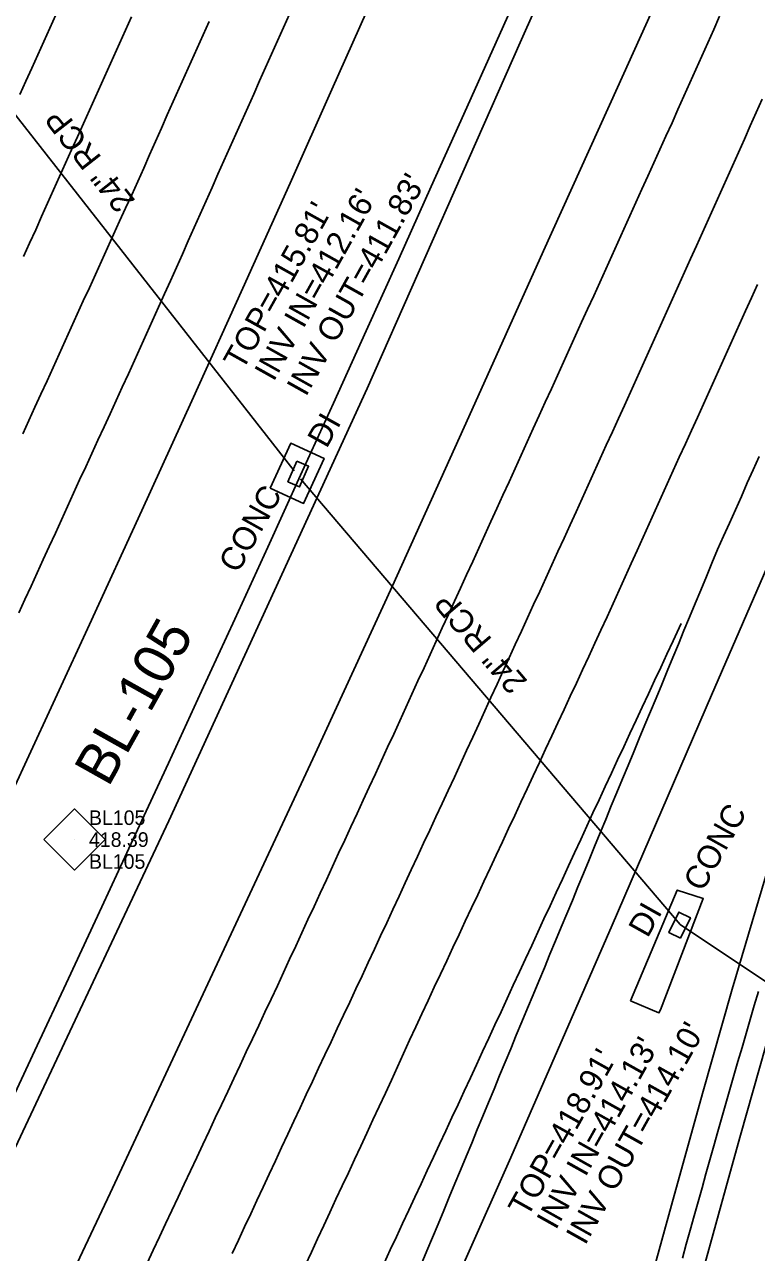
# Model space of a CAD drawing. Extents: x 2074109 to 2077820, y 741079 to 746031.
# Drawn here: x 2075964.7 to 2076090.1, y 744152.4 to 744362.7 of the extents above; entities that cross this region are included whole.
import ezdxf

# ---------------------------------------------------------------- set-up
doc = ezdxf.new("R2010")
doc.units = 0
for name, color, linetype in [('CTL Secondary Horizontal and Vertical CELL', 7, 'Continuous'), ('CTL Secondary Horizontal and Vertical Cogo Comment', 7, 'Continuous'), ('CTL Secondary Horizontal and Vertical Cogo Elevation', 7, 'Continuous'), ('CTL Secondary Horizontal and Vertical Cogo Number', 7, 'Continuous'), ('Exist Guardrail Cable Guide Rail', 7, 'Continuous'), ('Exist Horizontal Alignment', 7, 'Continuous'), ('Exist Horizontal Baseline Alignment Station Label', 7, 'Continuous'), ('Exist Roads EOP', 7, 'Continuous'), ('Exist Roads EOT', 7, 'Continuous'), ('Exist Structure Minor Drop Inlet', 7, 'Continuous'), ('Exist Structure Minor Drop Inlet Text', 7, 'Continuous'), ('Exist Structure Minor Drop Inlet Top Elevation', 7, 'Continuous'), ('Exist Structure Minor Paved Ditch or Gutter', 7, 'Continuous'), ('Exist Structure Minor Paved Ditch or Gutter Text', 7, 'Continuous'), ('Exist Structure Minor Pipes RCP 15 Inch', 7, 'Continuous'), ('Exist Structure Minor Pipes RCP 15 Inch Invert', 7, 'Continuous'), ('Exist Structure Minor Pipes RCP 24 Inch', 7, 'Continuous'), ('Exist Structure Minor Pipes RCP 24 Inch Invert', 7, 'Continuous'), ('Exist Structure Minor Pipes RCP 24 Inch Text', 7, 'Continuous')]:
    doc.layers.add(name, color=color, linetype=linetype)

msp = doc.modelspace()

# ---------------------------------------------------------------- linework, layer by layer
at = {"layer": 'CTL Secondary Horizontal and Vertical CELL'}
msp.add_line((2075973.22, 744223.13), (2075973.22, 744223.13), dxfattribs=at)
msp.add_lwpolyline([(2075968, 744223.15), (2075973.25, 744228.39), (2075978.5, 744223.14), (2075973.25, 744217.9)], close=True, dxfattribs=at)
at = {"layer": 'Exist Guardrail Cable Guide Rail'}
msp.add_lwpolyline([(2075948.31, 744139.02), (2075989.39, 744226.34), (2076023.39, 744300.35), (2076049.61, 744359.61), (2076088.84, 744447.64), (2076120.46, 744520.55), (2076157.81, 744608.48)], dxfattribs=at)
at = {"layer": 'Exist Horizontal Alignment'}
for centre, radius, start, end in [((2065746.77, 748969.72), 11283.45, 330.581241, 339.398504), ((2074798.58, 745361.18), 1469.76, 306.18995, 339.08912), ((2078824.82, 743400.1), 2844.34, 161.20687, 171.42865)]:
    msp.add_arc(centre, radius, start, end, dxfattribs=at)
at = {"layer": 'Exist Roads EOP'}
for points in [[(2076077.87, 744377.58), (2076066.3, 744351.92), (2076053.6, 744323.92), (2076040.8, 744295.48), (2076027.73, 744266.56), (2076014.5, 744237.8), (2076002.1, 744211.29), (2075990.51, 744186.45), (2075979.36, 744162.61), (2075967.54, 744137.56), (2075955.17, 744111.24)], [(2075952.83, 744210.32), (2075964.71, 744235.96), (2075975.8, 744259.95), (2075984.8, 744279.5), (2075993.35, 744298.22), (2076002.09, 744317.51), (2076010.19, 744335.52), (2076017.34, 744351.57), (2076024.53, 744367.7)], [(2076096.79, 744280.96), (2076082.4, 744247.87), (2076065.38, 744208.48), (2076047.99, 744168.72), (2076032.56, 744134.03)], [(2076070.12, 744140.88), (2076075.56, 744160.52), (2076080.83, 744179.63), (2076085.93, 744197.51), (2076092.78, 744220.6)]]:
    msp.add_lwpolyline(points, dxfattribs=at)
at = {"layer": 'Exist Roads EOT'}
for points in [[(2076010.08, 744364.46), (2076009.06, 744362.18), (2076008.04, 744359.9), (2076007.02, 744357.62), (2076005.99, 744355.34), (2076004.97, 744353.05), (2076003.95, 744350.77), (2076002.93, 744348.49), (2076001.91, 744346.21), (2076000.89, 744343.93), (2075999.87, 744341.64), (2075998.85, 744339.36), (2075997.83, 744337.08), (2075996.82, 744334.79), (2075995.8, 744332.51), (2075994.78, 744330.23), (2075993.76, 744327.94), (2075992.74, 744325.66), (2075991.73, 744323.38), (2075990.71, 744321.09), (2075989.68, 744318.81), (2075988.66, 744316.54), (2075987.63, 744314.26), (2075986.6, 744311.98), (2075985.57, 744309.7), (2075984.54, 744307.42), (2075983.52, 744305.14), (2075982.48, 744302.87), (2075981.43, 744300.6), (2075980.39, 744298.32), (2075979.35, 744296.05), (2075978.3, 744293.78), (2075977.26, 744291.51), (2075976.21, 744289.24), (2075975.17, 744286.97), (2075974.12, 744284.7), (2075973.08, 744282.43), (2075972.04, 744280.15), (2075971, 744277.88), (2075969.96, 744275.61), (2075968.92, 744273.33), (2075967.88, 744271.06), (2075966.84, 744268.79), (2075965.8, 744266.51), (2075964.76, 744264.24), (2075963.72, 744261.97)], [(2075963.89, 744350.68), (2075964.92, 744352.95), (2075965.94, 744355.23), (2075966.97, 744357.51), (2075968, 744359.79), (2075969.02, 744362.07), (2075970.05, 744364.35)], [(2075983.01, 744363.99), (2075981.99, 744361.71), (2075980.96, 744359.43), (2075979.94, 744357.15), (2075978.91, 744354.87), (2075977.89, 744352.59), (2075976.86, 744350.31), (2075975.83, 744348.03), (2075974.8, 744345.75), (2075973.77, 744343.47), (2075972.75, 744341.2), (2075971.72, 744338.92), (2075970.69, 744336.64), (2075969.67, 744334.36), (2075968.64, 744332.08), (2075967.61, 744329.8), (2075966.59, 744327.52), (2075965.56, 744325.24), (2075964.53, 744322.96)], [(2075985.67, 744150.58), (2075986.73, 744152.84), (2075987.8, 744155.11), (2075988.86, 744157.37), (2075989.92, 744159.63), (2075990.99, 744161.89), (2075992.05, 744164.15), (2075993.11, 744166.42), (2075994.18, 744168.68), (2075995.24, 744170.94), (2075996.3, 744173.2), (2075997.37, 744175.47), (2075998.43, 744177.73), (2075999.49, 744179.99), (2076000.56, 744182.25), (2076001.62, 744184.52), (2076002.68, 744186.78), (2076003.75, 744189.04), (2076004.81, 744191.3), (2076005.87, 744193.57), (2076006.93, 744195.83), (2076008, 744198.09), (2076009.05, 744200.36), (2076010.1, 744202.63), (2076011.15, 744204.9), (2076012.2, 744207.16), (2076013.25, 744209.43), (2076014.3, 744211.7), (2076015.35, 744213.97), (2076016.4, 744216.24), (2076017.45, 744218.51), (2076018.5, 744220.78), (2076019.55, 744223.04), (2076020.61, 744225.31), (2076021.66, 744227.58), (2076022.71, 744229.85), (2076023.76, 744232.12), (2076024.81, 744234.39), (2076025.85, 744236.66), (2076026.89, 744238.93), (2076027.94, 744241.2), (2076028.98, 744243.47), (2076030.02, 744245.75), (2076031.06, 744248.02), (2076032.1, 744250.29), (2076033.14, 744252.56), (2076034.18, 744254.84), (2076035.22, 744257.11), (2076036.27, 744259.38), (2076037.31, 744261.66), (2076038.35, 744263.93), (2076039.39, 744266.2), (2076040.43, 744268.47), (2076041.47, 744270.75), (2076042.51, 744273.02), (2076043.55, 744275.29), (2076044.59, 744277.57), (2076045.62, 744279.84), (2076046.66, 744282.12), (2076047.7, 744284.39), (2076048.74, 744286.67), (2076049.77, 744288.94), (2076050.81, 744291.21), (2076051.85, 744293.49), (2076052.89, 744295.76), (2076053.92, 744298.04), (2076054.96, 744300.31), (2076056, 744302.59), (2076057.04, 744304.86), (2076058.07, 744307.14), (2076059.11, 744309.41), (2076060.14, 744311.69), (2076061.17, 744313.96), (2076062.21, 744316.24), (2076063.24, 744318.52), (2076064.27, 744320.79), (2076065.3, 744323.07), (2076066.34, 744325.35), (2076067.37, 744327.62), (2076068.4, 744329.9), (2076069.43, 744332.18), (2076070.47, 744334.46), (2076071.5, 744336.73), (2076072.53, 744339.01), (2076073.56, 744341.29), (2076074.59, 744343.56), (2076075.63, 744345.84), (2076076.65, 744348.12), (2076077.67, 744350.4), (2076078.69, 744352.68), (2076079.71, 744354.97), (2076080.73, 744357.25), (2076081.75, 744359.53), (2076082.77, 744361.82), (2076083.79, 744364.1)], [(2075964.39, 744292.59), (2075965.43, 744294.86), (2075966.46, 744297.14), (2075967.5, 744299.41), (2075968.54, 744301.68), (2075969.57, 744303.96), (2075970.6, 744306.24), (2075971.64, 744308.51), (2075972.67, 744310.79), (2075973.71, 744313.06), (2075974.75, 744315.34), (2075975.79, 744317.61), (2075976.82, 744319.89), (2075977.86, 744322.16), (2075978.9, 744324.44), (2075979.93, 744326.71), (2075980.97, 744328.99), (2075982.01, 744331.26), (2075983.04, 744333.53), (2075984.08, 744335.81), (2075985.12, 744338.08), (2075986.12, 744340.37), (2075987.13, 744342.66), (2075988.13, 744344.95), (2075989.14, 744347.24), (2075990.16, 744349.52), (2075991.19, 744351.8), (2075992.21, 744354.08), (2075993.23, 744356.36), (2075994.26, 744358.64), (2075995.28, 744360.92), (2075996.3, 744363.21)], [(2076091.09, 744349.9), (2076090.07, 744347.61), (2076089.04, 744345.33), (2076088.02, 744343.05), (2076087, 744340.77), (2076085.97, 744338.49), (2076084.95, 744336.21), (2076083.92, 744333.93), (2076082.9, 744331.65), (2076081.87, 744329.37), (2076080.84, 744327.09), (2076079.82, 744324.81), (2076078.79, 744322.54), (2076077.76, 744320.26), (2076076.73, 744317.98), (2076075.7, 744315.7), (2076074.67, 744313.42), (2076073.64, 744311.14), (2076072.61, 744308.87), (2076071.59, 744306.59), (2076070.56, 744304.31), (2076069.53, 744302.03), (2076068.5, 744299.75), (2076067.47, 744297.47), (2076066.44, 744295.2), (2076065.41, 744292.92), (2076064.37, 744290.65), (2076063.33, 744288.37), (2076062.3, 744286.1), (2076061.26, 744283.82), (2076060.23, 744281.55), (2076059.19, 744279.27), (2076058.15, 744277), (2076057.12, 744274.72), (2076056.08, 744272.44), (2076055.05, 744270.17), (2076054.01, 744267.89), (2076052.97, 744265.62), (2076051.92, 744263.35), (2076050.88, 744261.08), (2076049.83, 744258.81), (2076048.78, 744256.54), (2076047.74, 744254.27), (2076046.69, 744252), (2076045.65, 744249.73), (2076044.61, 744247.46), (2076043.56, 744245.18), (2076042.52, 744242.91), (2076041.47, 744240.64), (2076040.43, 744238.37), (2076039.38, 744236.1), (2076038.34, 744233.83), (2076037.29, 744231.56), (2076036.24, 744229.29), (2076035.18, 744227.03), (2076034.12, 744224.76), (2076033.06, 744222.5), (2076032.01, 744220.23), (2076030.95, 744217.96), (2076029.9, 744215.7), (2076028.85, 744213.43), (2076027.79, 744211.16), (2076026.74, 744208.9), (2076025.69, 744206.63), (2076024.63, 744204.36), (2076023.58, 744202.1), (2076022.52, 744199.83), (2076021.47, 744197.56), (2076020.42, 744195.3), (2076019.34, 744193.04), (2076018.27, 744190.78), (2076017.2, 744188.52), (2076016.13, 744186.26), (2076015.07, 744184), (2076014.02, 744181.73), (2076012.96, 744179.47), (2076011.9, 744177.2), (2076010.84, 744174.94), (2076009.79, 744172.67), (2076008.73, 744170.4), (2076007.67, 744168.14), (2076006.61, 744165.87), (2076005.56, 744163.61), (2076004.5, 744161.34), (2076003.44, 744159.08), (2076002.39, 744156.81), (2076001.33, 744154.55), (2076000.27, 744152.28)], [(2076090.3, 744318.19), (2076089.27, 744315.91), (2076088.24, 744313.64), (2076087.21, 744311.36), (2076086.18, 744309.08), (2076085.15, 744306.8), (2076084.12, 744304.52), (2076083.09, 744302.25), (2076082.06, 744299.97), (2076081.03, 744297.69), (2076079.99, 744295.42), (2076078.95, 744293.14), (2076077.91, 744290.87), (2076076.88, 744288.59), (2076075.85, 744286.32), (2076074.82, 744284.04), (2076073.78, 744281.76), (2076072.75, 744279.48), (2076071.72, 744277.21), (2076070.69, 744274.93), (2076069.66, 744272.65), (2076068.62, 744270.38), (2076067.59, 744268.1), (2076066.56, 744265.82), (2076065.53, 744263.55), (2076064.49, 744261.27), (2076063.44, 744259), (2076062.4, 744256.73), (2076061.35, 744254.46), (2076060.3, 744252.19), (2076059.24, 744249.93), (2076058.19, 744247.66), (2076057.13, 744245.4), (2076056.07, 744243.13), (2076055.01, 744240.87), (2076053.96, 744238.6), (2076052.9, 744236.34), (2076051.84, 744234.07), (2076050.79, 744231.8), (2076049.73, 744229.54), (2076048.67, 744227.27), (2076047.62, 744225.01), (2076046.56, 744222.74), (2076045.51, 744220.48), (2076044.45, 744218.21), (2076043.39, 744215.95), (2076042.33, 744213.68), (2076041.27, 744211.42), (2076040.2, 744209.16), (2076039.14, 744206.89), (2076038.08, 744204.63), (2076037.02, 744202.37), (2076035.96, 744200.1), (2076034.9, 744197.84), (2076033.83, 744195.58), (2076032.77, 744193.31), (2076031.71, 744191.05), (2076030.67, 744188.78), (2076029.63, 744186.5), (2076028.6, 744184.23), (2076027.56, 744181.95), (2076026.51, 744179.69), (2076025.45, 744177.42), (2076024.39, 744175.16), (2076023.34, 744172.89), (2076022.28, 744170.62), (2076021.22, 744168.36), (2076020.17, 744166.09), (2076019.11, 744163.83), (2076018.05, 744161.56), (2076017, 744159.3), (2076015.94, 744157.03), (2076014.89, 744154.77), (2076013.83, 744152.5), (2076012.78, 744150.23)], [(2076090.58, 744288.74), (2076089.56, 744286.46), (2076088.53, 744284.18), (2076087.51, 744281.89), (2076086.49, 744279.61), (2076085.47, 744277.33), (2076084.45, 744275.05), (2076083.43, 744272.77), (2076082.47, 744270.46), (2076081.51, 744268.15), (2076080.55, 744265.84), (2076079.6, 744263.53), (2076078.64, 744261.22), (2076077.68, 744258.91), (2076076.73, 744256.6), (2076075.77, 744254.29), (2076074.81, 744251.98), (2076073.86, 744249.67), (2076072.9, 744247.36), (2076071.94, 744245.06), (2076070.98, 744242.75), (2076070.02, 744240.44), (2076069.06, 744238.13), (2076068.1, 744235.83), (2076067.13, 744233.52), (2076066.17, 744231.21), (2076065.22, 744228.9), (2076064.27, 744226.59), (2076063.32, 744224.27), (2076062.37, 744221.96), (2076061.42, 744219.65), (2076060.46, 744217.34), (2076059.51, 744215.03), (2076058.55, 744212.72), (2076057.59, 744210.41), (2076056.63, 744208.11), (2076055.67, 744205.8), (2076054.71, 744203.49), (2076053.75, 744201.18), (2076052.79, 744198.87), (2076051.83, 744196.56), (2076050.87, 744194.26), (2076049.91, 744191.95), (2076048.95, 744189.64), (2076047.99, 744187.33), (2076047.04, 744185.02), (2076046.08, 744182.71), (2076045.13, 744180.4), (2076044.17, 744178.09), (2076043.21, 744175.78), (2076042.26, 744173.47), (2076041.3, 744171.16), (2076040.35, 744168.85), (2076039.39, 744166.54), (2076038.44, 744164.23), (2076037.47, 744161.92), (2076036.51, 744159.62), (2076035.54, 744157.31), (2076034.58, 744155.01), (2076033.61, 744152.7), (2076032.65, 744150.4)], [(2076026.28, 744150.61), (2076027.34, 744152.87), (2076028.39, 744155.14), (2076029.45, 744157.4), (2076030.51, 744159.67), (2076031.57, 744161.93), (2076032.62, 744164.2), (2076033.68, 744166.46), (2076034.74, 744168.73), (2076035.8, 744170.99), (2076036.86, 744173.26), (2076037.91, 744175.52), (2076038.97, 744177.79), (2076040.02, 744180.05), (2076041.08, 744182.32), (2076042.13, 744184.59), (2076043.18, 744186.86), (2076044.23, 744189.13), (2076045.28, 744191.39), (2076046.33, 744193.66), (2076047.38, 744195.93), (2076048.43, 744198.2), (2076049.48, 744200.47), (2076050.54, 744202.73), (2076051.59, 744205), (2076052.64, 744207.27), (2076053.69, 744209.54), (2076054.74, 744211.81), (2076055.79, 744214.08), (2076056.84, 744216.35), (2076057.88, 744218.61), (2076058.93, 744220.88), (2076059.98, 744223.15), (2076061.03, 744225.42), (2076062.08, 744227.69), (2076063.13, 744229.96), (2076064.18, 744232.23), (2076065.24, 744234.49), (2076066.29, 744236.76), (2076067.35, 744239.02), (2076068.41, 744241.29), (2076069.47, 744243.55), (2076070.53, 744245.82), (2076071.58, 744248.08), (2076072.64, 744250.35), (2076073.7, 744252.61), (2076074.76, 744254.88), (2076075.82, 744257.14), (2076076.87, 744259.41), (2076077.2, 744260.11)], [(2076077.43, 744151.46), (2076078.08, 744153.87), (2076078.75, 744156.28), (2076079.42, 744158.69), (2076080.09, 744161.1), (2076080.77, 744163.5), (2076081.44, 744165.91), (2076082.11, 744168.32), (2076082.79, 744170.72), (2076083.46, 744173.13), (2076084.15, 744175.53), (2076084.85, 744177.93), (2076085.54, 744180.33), (2076086.23, 744182.74), (2076086.92, 744185.14), (2076087.62, 744187.54), (2076088.31, 744189.94), (2076089.02, 744192.34), (2076089.73, 744194.73), (2076090.43, 744197.13)]]:
    msp.add_lwpolyline(points, dxfattribs=at)
at = {"layer": 'Exist Structure Minor Drop Inlet'}
for points in [[(2076011.34, 744287.92), (2076009.8, 744284.38), (2076011.8, 744283.51), (2076013.34, 744287.04)], [(2076077.07, 744206.23), (2076078.77, 744209.75), (2076076.79, 744210.71), (2076075.09, 744207.2)]]:
    msp.add_lwpolyline(points, close=True, dxfattribs=at)
at = {"layer": 'Exist Structure Minor Paved Ditch or Gutter'}
msp.add_lwpolyline([(2076006.79, 744283.28), (2076010.29, 744290.98), (2076016.01, 744288.38), (2076012.51, 744280.68)], close=True, dxfattribs=at)
msp.add_lwpolyline([(2076068.5, 744195.52), (2076076.53, 744214.49), (2076080.97, 744213.05), (2076073.63, 744194), (2076073.38, 744193.44), (2076068.5, 744195.52)], dxfattribs=at)
at = {"layer": 'Exist Structure Minor Pipes RCP 15 Inch'}
msp.add_line((2076077.02, 744208.59), (2076127.72, 744174.77), dxfattribs=at)
at = {"layer": 'Exist Structure Minor Pipes RCP 24 Inch'}
for p, q in [((2075944.79, 744370.57), (2076010.87, 744286.26)), ((2076011.99, 744284.92), (2076077.02, 744208.61))]:
    msp.add_line(p, q, dxfattribs=at)

# ---------------------------------------------------------------- texts
at = {"layer": 'CTL Secondary Horizontal and Vertical Cogo Comment'}
msp.add_text('BL105', height=2.5, dxfattribs=at).set_placement((2075975.72, 744218.13))
at = {"layer": 'CTL Secondary Horizontal and Vertical Cogo Elevation'}
msp.add_text('418.39', height=2.5, dxfattribs=at).set_placement((2075975.72, 744221.88))
at = {"layer": 'CTL Secondary Horizontal and Vertical Cogo Number'}
msp.add_text('BL105', height=2.5, dxfattribs=at).set_placement((2075975.72, 744225.63))
at = {"layer": 'Exist Horizontal Baseline Alignment Station Label'}
msp.add_text('BL-105', height=7, rotation=60.742, dxfattribs=at).set_placement((2075979.04, 744231.95))
at = {"layer": 'Exist Structure Minor Drop Inlet Text'}
for p in [(2076016.44, 744289.95), (2076071.45, 744206.15)]:
    msp.add_text('DI', height=4, rotation=60.7411, dxfattribs=at).set_placement(p)
at = {"layer": 'Exist Structure Minor Drop Inlet Top Elevation'}
for s, p in [("TOP=415.81'", (2076002.06, 744303.28)), ("TOP=418.91'", (2076050.85, 744158.28))]:
    msp.add_text(s, height=4, rotation=60.7411, dxfattribs=at).set_placement(p)
at = {"layer": 'Exist Structure Minor Paved Ditch or Gutter Text'}
for p in [(2076001.24, 744268.55), (2076080.86, 744214.02)]:
    msp.add_text('CONC', height=4, rotation=60.742, dxfattribs=at).set_placement(p)
at = {"layer": 'Exist Structure Minor Pipes RCP 15 Inch Invert'}
msp.add_text("INV IN=414.13'", height=4, rotation=60.7411, dxfattribs=at).set_placement((2076055.71, 744156.16))
at = {"layer": 'Exist Structure Minor Pipes RCP 24 Inch Invert'}
for s, p in [("INV OUT=411.83'", (2076012.89, 744298.82)), ("INV IN=412.16'", (2076007.37, 744301.4)), ("INV OUT=414.10'", (2076060.74, 744153.54))]:
    msp.add_text(s, height=4, rotation=60.7411, dxfattribs=at).set_placement(p)
at = {"layer": 'Exist Structure Minor Pipes RCP 24 Inch Text'}
for rotation, p in [(128.0894, (2075983.77, 744332.52)), (130.4393, (2076051, 744250.25))]:
    msp.add_text('24" RCP', height=4, rotation=rotation, dxfattribs=at).set_placement(p)

doc.saveas('drawing.dxf')
